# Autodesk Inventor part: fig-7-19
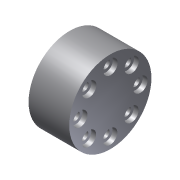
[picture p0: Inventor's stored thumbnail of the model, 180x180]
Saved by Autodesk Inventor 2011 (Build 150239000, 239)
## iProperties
Created: 2004-05
Part Number: fig-7-19
Document SubType Name: Modeling
Designer: CADCIM Technologies
Manufacturer: Standard
Standards Organization: Custom
Density: 1 g/cm^3
Author: CADCIM Technologies
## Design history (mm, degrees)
sketch "Sketch1"
  geometry: C1 r 17.175 at (0, 0)
  constraints: 1 centre point
extrude "Extrusion1" new body sketch "Sketch1" distance "d0" = 17; taper "d1" = 0 deg
sketch "Sketch2"
  geometry: 1 further point
hole "Hole1" sketch "Sketch2" at (12.571, -0.074) diameter "d2" = 3.5; stored, may be unused: countersink angle "d6" = 90 deg, drill point angle "d8" = 118 deg; dims "d3" = 6, "d4" = 6, "d5" = 2, "d7" = 8
pattern_circular "Circular Pattern1" dims angle "d11" = 360 deg
body "Solid1"
